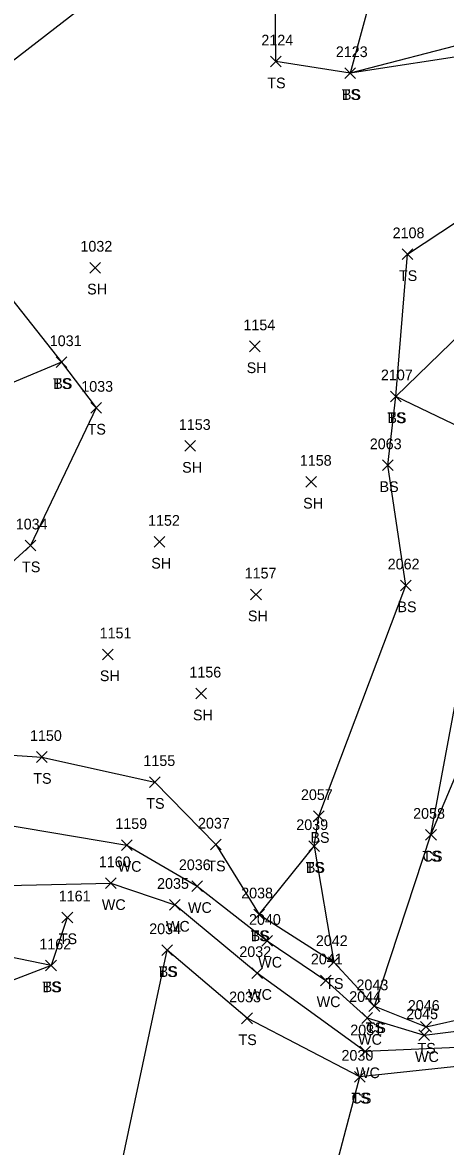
# Model space of a CAD drawing. Extents: x 1551995 to 1555700, y 777276 to 783130.
# Drawn here: x 1555046.7 to 1555125.8, y 778001.3 to 778211.4 of the extents above; entities that cross this region are included whole.
import ezdxf

# ---------------------------------------------------------------- set-up
doc = ezdxf.new("R2010")
doc.units = 0
for name, color, linetype in [('L_A', 7, 'Continuous'), ('L_I', 7, 'Continuous'), ('L_TIC', 7, 'Continuous'), ('LAWA', 7, 'Continuous'), ('LAWE', 7, 'Continuous'), ('LELB', 7, 'Continuous')]:
    doc.layers.add(name, color=color, linetype=linetype)

msp = doc.modelspace()

# ---------------------------------------------------------------- linework, layer by layer
at = {"layer": 'L_TIC'}
for points in [[(1555093.09, 778203.05), (1555095.09, 778205.05)], [(1555095.09, 778203.05), (1555093.09, 778205.05)], [(1555107, 778200.88), (1555109, 778202.88)], [(1555109, 778200.88), (1555107, 778202.88)], [(1555107, 778200.88), (1555109, 778202.88)], [(1555109, 778200.88), (1555107, 778202.88)], [(1555107, 778200.88), (1555109, 778202.88)], [(1555109, 778200.88), (1555107, 778202.88)], [(1555117.7, 778167.03), (1555119.7, 778169.03)], [(1555119.7, 778167.03), (1555117.7, 778169.03)], [(1555059.34, 778164.52), (1555061.34, 778166.52)], [(1555061.34, 778164.52), (1555059.34, 778166.52)], [(1555089.16, 778149.82), (1555091.16, 778151.82)], [(1555091.16, 778149.82), (1555089.16, 778151.82)], [(1555053.04, 778146.86), (1555055.04, 778148.86)], [(1555055.04, 778146.86), (1555053.04, 778148.86)], [(1555053.04, 778146.86), (1555055.04, 778148.86)], [(1555055.04, 778146.86), (1555053.04, 778148.86)], [(1555115.51, 778140.47), (1555117.51, 778142.47)], [(1555117.51, 778140.47), (1555115.51, 778142.47)], [(1555115.51, 778140.47), (1555117.51, 778142.47)], [(1555117.51, 778140.47), (1555115.51, 778142.47)], [(1555059.5, 778138.33), (1555061.5, 778140.33)], [(1555061.5, 778138.33), (1555059.5, 778140.33)], [(1555077.1, 778131.2), (1555079.1, 778133.2)], [(1555079.1, 778131.2), (1555077.1, 778133.2)], [(1555114.04, 778127.59), (1555116.04, 778129.59)], [(1555116.04, 778127.59), (1555114.04, 778129.59)], [(1555099.71, 778124.5), (1555101.71, 778126.5)], [(1555101.71, 778124.5), (1555099.71, 778126.5)], [(1555047.25, 778112.6), (1555049.25, 778114.6)], [(1555049.25, 778112.6), (1555047.25, 778114.6)], [(1555071.33, 778113.28), (1555073.33, 778115.28)], [(1555073.33, 778113.28), (1555071.33, 778115.28)], [(1555117.39, 778105.13), (1555119.39, 778107.13)], [(1555119.39, 778105.13), (1555117.39, 778107.13)], [(1555089.39, 778103.43), (1555091.39, 778105.43)], [(1555091.39, 778103.43), (1555089.39, 778105.43)], [(1555061.72, 778092.24), (1555063.72, 778094.24)], [(1555063.72, 778092.24), (1555061.72, 778094.24)], [(1555079.12, 778084.92), (1555081.12, 778086.92)], [(1555081.12, 778084.92), (1555079.12, 778086.92)], [(1555049.35, 778073.06), (1555051.35, 778075.06)], [(1555051.35, 778073.06), (1555049.35, 778075.06)], [(1555070.47, 778068.38), (1555072.47, 778070.38)], [(1555072.47, 778068.38), (1555070.47, 778070.38)], [(1555101.13, 778062.02), (1555103.13, 778064.02)], [(1555103.13, 778062.02), (1555101.13, 778064.02)], [(1555065.22, 778056.61), (1555067.22, 778058.61)], [(1555067.22, 778056.61), (1555065.22, 778058.61)], [(1555081.88, 778056.69), (1555083.88, 778058.69)], [(1555083.88, 778056.69), (1555081.88, 778058.69)], [(1555122.1, 778058.52), (1555124.1, 778060.52)], [(1555124.1, 778058.52), (1555122.1, 778060.52)], [(1555122.1, 778058.52), (1555124.1, 778060.52)], [(1555124.1, 778058.52), (1555122.1, 778060.52)], [(1555100.27, 778056.41), (1555102.27, 778058.41)], [(1555102.27, 778056.41), (1555100.27, 778058.41)], [(1555100.27, 778056.41), (1555102.27, 778058.41)], [(1555102.27, 778056.41), (1555100.27, 778058.41)], [(1555062.27, 778049.47), (1555064.27, 778051.47)], [(1555064.27, 778049.47), (1555062.27, 778051.47)], [(1555078.37, 778048.92), (1555080.37, 778050.92)], [(1555080.37, 778048.92), (1555078.37, 778050.92)], [(1555074.24, 778045.42), (1555076.24, 778047.42)], [(1555076.24, 778045.42), (1555074.24, 778047.42)], [(1555074.24, 778045.42), (1555076.24, 778047.42)], [(1555076.24, 778045.42), (1555074.24, 778047.42)], [(1555054.12, 778043.08), (1555056.12, 778045.08)], [(1555056.12, 778043.08), (1555054.12, 778045.08)], [(1555054.12, 778043.08), (1555056.12, 778045.08)], [(1555056.12, 778043.08), (1555054.12, 778045.08)], [(1555089.96, 778043.64), (1555091.96, 778045.64)], [(1555091.96, 778043.64), (1555089.96, 778045.64)], [(1555089.96, 778043.64), (1555091.96, 778045.64)], [(1555091.96, 778043.64), (1555089.96, 778045.64)], [(1555091.5, 778038.7), (1555093.5, 778040.7)], [(1555093.5, 778038.7), (1555091.5, 778040.7)], [(1555072.77, 778036.95), (1555074.77, 778038.95)], [(1555074.77, 778036.95), (1555072.77, 778038.95)], [(1555072.77, 778036.95), (1555074.77, 778038.95)], [(1555074.77, 778036.95), (1555072.77, 778038.95)], [(1555051.07, 778034.1), (1555053.07, 778036.1)], [(1555053.07, 778034.1), (1555051.07, 778036.1)], [(1555051.07, 778034.1), (1555053.07, 778036.1)], [(1555053.07, 778034.1), (1555051.07, 778036.1)], [(1555103.92, 778034.73), (1555105.92, 778036.73)], [(1555105.92, 778034.73), (1555103.92, 778036.73)], [(1555103.92, 778034.73), (1555105.92, 778036.73)], [(1555105.92, 778034.73), (1555103.92, 778036.73)], [(1555089.6, 778032.68), (1555091.6, 778034.68)], [(1555091.6, 778032.68), (1555089.6, 778034.68)], [(1555102.43, 778031.31), (1555104.43, 778033.31)], [(1555104.43, 778031.31), (1555102.43, 778033.31)], [(1555111.51, 778026.47), (1555113.51, 778028.47)], [(1555113.51, 778026.47), (1555111.51, 778028.47)], [(1555111.51, 778026.47), (1555113.51, 778028.47)], [(1555113.51, 778026.47), (1555111.51, 778028.47)], [(1555087.71, 778024.22), (1555089.71, 778026.22)], [(1555089.71, 778024.22), (1555087.71, 778026.22)], [(1555110.16, 778024.28), (1555112.16, 778026.28)], [(1555112.16, 778024.28), (1555110.16, 778026.28)], [(1555120.81, 778021.05), (1555122.81, 778023.05)], [(1555122.81, 778021.05), (1555120.81, 778023.05)], [(1555121.17, 778022.62), (1555123.17, 778024.62)], [(1555123.17, 778022.62), (1555121.17, 778024.62)], [(1555109.79, 778018.04), (1555111.79, 778020.04)], [(1555111.79, 778018.04), (1555109.79, 778020.04)], [(1555108.8, 778013.3), (1555110.8, 778015.3)], [(1555110.8, 778013.3), (1555108.8, 778015.3)], [(1555108.8, 778013.3), (1555110.8, 778015.3)], [(1555110.8, 778013.3), (1555108.8, 778015.3)]]:
    msp.add_lwpolyline(points, dxfattribs=at)
at = {"layer": 'LAWA'}
msp.add_lwpolyline([(1555085.12, 778246.6), (1555062.11, 778217.51), (1555036.75, 778197.89), (1555030.02, 778178.79), (1555023.09, 778154.13), (1555005.22, 778133.85), (1555000.72, 778121.06), (1554983.85, 778091.44), (1554975.19, 778092.03), (1554970.99, 778074.93), (1554967.22, 778059.88), (1554967.17, 778023.98), (1554956.28, 777979.25), (1554949.24, 777950.5), (1554942.15, 777917.97), (1554937.88, 777884.35), (1554924.17, 777845.95), (1554911.99, 777797.39)], dxfattribs=at)
at = {"layer": 'LAWE'}
for points in [[(1554980.98, 778087.61), (1554986.81, 778080.45), (1554995.57, 778075.14), (1555006.25, 778070.66), (1555023.38, 778064.79), (1555066.22, 778057.61), (1555079.37, 778049.92), (1555092.5, 778039.7), (1555103.43, 778032.31), (1555111.16, 778025.28), (1555121.81, 778022.05), (1555131.79, 778023.3), (1555142.1, 778032.9), (1555159.88, 778037.39), (1555175.92, 778041.48), (1555190.31, 778048.94), (1555221.06, 778078.31), (1555223.43, 778108.97), (1555239.75, 778121.69), (1555250.77, 778129.37)], [(1554980.98, 778087.61), (1554973.68, 778078.88), (1554981.3, 778074.53), (1554990.85, 778069.35), (1555006.46, 778065.69), (1555021.52, 778049.53), (1555063.27, 778050.47), (1555075.24, 778046.42)], [(1555183.22, 778032.67), (1555178.02, 778035.09), (1555156.47, 778032.2), (1555133.72, 778020.04), (1555110.79, 778019.04), (1555090.6, 778033.68), (1555075.24, 778046.42)]]:
    msp.add_lwpolyline(points, dxfattribs=at)
at = {"layer": 'LELB'}
for points in [[(1555123.69, 778250.13), (1555114.06, 778224.11), (1555108, 778201.88)], [(1555135, 778132.57), (1555116.51, 778141.47), (1555118.7, 778168.03), (1555150.02, 778188.76), (1555163.14, 778194.26), (1555166.5, 778216.38), (1555151.21, 778212.18), (1555132.34, 778205.59), (1555108, 778201.88), (1555094.09, 778204.05), (1555093.66, 778246.97)], [(1555090.96, 778044.64), (1555101.27, 778057.41), (1555102.13, 778063.02), (1555118.39, 778106.13), (1555115.04, 778128.59), (1555116.51, 778141.47), (1555141.3, 778165.52), (1555169.36, 778182.3), (1555182.25, 778189.59), (1555182.94, 778207.75), (1555171.93, 778222.3), (1555147.47, 778218.47), (1555131.09, 778207.87), (1555108, 778201.88)], [(1555030.02, 778178.79), (1555043.74, 778160.89), (1555054.04, 778147.86), (1555060.5, 778139.33), (1555048.25, 778113.6), (1555032.66, 778099.46), (1555025.51, 778075.72)], [(1555054.04, 778147.86), (1555024.71, 778135.57), (1555012.44, 778130.42), (1555000.72, 778121.06)], [(1555123.1, 778059.52), (1555129.25, 778092.59), (1555136.4, 778099.01), (1555143.77, 778110.63), (1555141.74, 778122.27)], [(1555112.51, 778027.47), (1555123.1, 778059.52), (1555138.09, 778095.14), (1555145.96, 778102.19)], [(1554988.34, 778085.79), (1554999.52, 778081.03), (1555010.57, 778076.63), (1555025.51, 778075.72), (1555050.35, 778074.06), (1555071.47, 778069.38), (1555082.88, 778057.69), (1555090.96, 778044.64), (1555104.92, 778035.73), (1555112.51, 778027.47), (1555122.17, 778023.62), (1555130.48, 778025.48), (1555140.65, 778033.87), (1555161.85, 778040.13), (1555175.62, 778046.97), (1555180.05, 778050.72)], [(1555101.27, 778057.41), (1555104.92, 778035.73)], [(1555055.12, 778044.08), (1555052.07, 778035.1), (1555029.38, 778026.34), (1555024.68, 778011.22), (1555010.67, 778012.71), (1554998.88, 778006.35)], [(1555052.07, 778035.1), (1555032.4, 778039.15), (1555013.66, 778029.98), (1554992.41, 778018.12), (1554987.13, 778004.53)], [(1555063.9, 777991.43), (1555073.77, 778037.95)], [(1555176.87, 778032.18), (1555160.69, 778028.02), (1555134.94, 778016.95), (1555109.8, 778014.3), (1555088.71, 778025.22), (1555073.77, 778037.95)], [(1555098.62, 777972.03), (1555109.8, 778014.3)]]:
    msp.add_lwpolyline(points, dxfattribs=at)

# ---------------------------------------------------------------- texts
at = {"layer": 'L_A'}
for s, p in [('TS', (1555092.5, 778199.05)), ('TS', (1555106.41, 778196.88)), ('BS', (1555106.45, 778196.88)), ('BS', (1555106.45, 778196.88)), ('TS', (1555117.11, 778163.03)), ('SH', (1555058.83, 778160.52)), ('SH', (1555088.65, 778145.82)), ('TS', (1555052.45, 778142.86)), ('BS', (1555052.48, 778142.86)), ('TS', (1555114.92, 778136.47)), ('BS', (1555114.95, 778136.47)), ('TS', (1555058.91, 778134.33)), ('SH', (1555076.59, 778127.2)), ('BS', (1555113.48, 778123.59)), ('SH', (1555099.2, 778120.5)), ('SH', (1555070.82, 778109.28)), ('TS', (1555046.66, 778108.6)), ('BS', (1555116.83, 778101.13)), ('SH', (1555088.88, 778099.43)), ('SH', (1555061.2, 778088.24)), ('SH', (1555078.61, 778080.92)), ('TS', (1555048.76, 778069.06)), ('TS', (1555069.88, 778064.38)), ('BS', (1555100.57, 778058.02)), ('TS', (1555121.51, 778054.52)), ('CS', (1555121.54, 778054.52)), ('WC', (1555064.53, 778052.61)), ('TS', (1555081.29, 778052.69)), ('TS', (1555099.68, 778052.41)), ('BS', (1555099.71, 778052.41)), ('WC', (1555061.57, 778045.47)), ('WC', (1555077.67, 778044.92)), ('WC', (1555073.55, 778041.42)), ('WC', (1555073.55, 778041.42)), ('TS', (1555053.53, 778039.08)), ('TS', (1555053.53, 778039.08)), ('TS', (1555089.37, 778039.64)), ('BS', (1555089.4, 778039.64)), ('WC', (1555090.81, 778034.7)), ('TS', (1555072.18, 778032.95)), ('BS', (1555072.21, 778032.95)), ('TS', (1555050.48, 778030.1)), ('BS', (1555050.51, 778030.1)), ('TS', (1555103.33, 778030.73)), ('TS', (1555103.33, 778030.73)), ('WC', (1555088.91, 778028.68)), ('WC', (1555101.73, 778027.31)), ('TS', (1555110.92, 778022.47)), ('CS', (1555110.95, 778022.47)), ('TS', (1555087.12, 778020.22)), ('WC', (1555109.47, 778020.28)), ('WC', (1555120.11, 778017.05)), ('TS', (1555120.58, 778018.62)), ('WC', (1555109.09, 778014.04)), ('TS', (1555108.21, 778009.3)), ('CS', (1555108.24, 778009.3))]:
    msp.add_text(s, height=2, dxfattribs=at).set_placement(p)
at = {"layer": 'L_I'}
for s, p in [('2124', (1555091.39, 778207.05)), ('2123', (1555105.31, 778204.88)), ('2123', (1555105.31, 778204.88)), ('2123', (1555105.31, 778204.88)), ('2108', (1555115.93, 778171.03)), ('1032', (1555057.57, 778168.52)), ('1154', (1555088.04, 778153.82)), ('1031', (1555051.84, 778150.86)), ('1031', (1555051.84, 778150.86)), ('2107', (1555113.74, 778144.47)), ('2107', (1555113.74, 778144.47)), ('1033', (1555057.73, 778142.33)), ('1153', (1555075.97, 778135.2)), ('2063', (1555111.66, 778131.59)), ('1158', (1555098.58, 778128.5)), ('1034', (1555045.48, 778116.6)), ('1152', (1555070.21, 778117.28)), ('2062', (1555115.01, 778109.13)), ('1157', (1555088.27, 778107.43)), ('1151', (1555061.16, 778096.24)), ('1156', (1555077.94, 778088.92)), ('1150', (1555048.14, 778077.06)), ('1155', (1555069.34, 778072.38)), ('2057', (1555098.79, 778066.02)), ('2058', (1555119.76, 778062.52)), ('2058', (1555119.76, 778062.52)), ('1159', (1555064.09, 778060.61)), ('2037', (1555079.54, 778060.69)), ('2039', (1555097.92, 778060.41)), ('2039', (1555097.92, 778060.41)), ('1160', (1555061.01, 778053.47)), ('2036', (1555075.97, 778052.92)), ('2035', (1555071.9, 778049.42)), ('2035', (1555071.9, 778049.42)), ('1161', (1555053.52, 778047.08)), ('1161', (1555053.52, 778047.08)), ('2038', (1555087.62, 778047.64)), ('2038', (1555087.62, 778047.64)), ('2040', (1555089.08, 778042.7)), ('2034', (1555070.43, 778040.95)), ('2034', (1555070.43, 778040.95)), ('1162', (1555049.89, 778038.1)), ('1162', (1555049.89, 778038.1)), ('2042', (1555101.58, 778038.73)), ('2042', (1555101.58, 778038.73)), ('2032', (1555087.27, 778036.68)), ('2041', (1555100.65, 778035.31)), ('2043', (1555109.17, 778030.47)), ('2043', (1555109.17, 778030.47)), ('2033', (1555085.37, 778028.22)), ('2044', (1555107.82, 778028.28)), ('2045', (1555118.47, 778025.05)), ('2046', (1555118.77, 778026.62)), ('2031', (1555108.01, 778022.04)), ('2030', (1555106.37, 778017.3)), ('2030', (1555106.37, 778017.3))]:
    msp.add_text(s, height=2, dxfattribs=at).set_placement(p)

doc.saveas('drawing.dxf')
